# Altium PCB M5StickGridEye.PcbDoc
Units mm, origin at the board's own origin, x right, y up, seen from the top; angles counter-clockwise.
Board outline 20 x 22 mm, 2 copper layers (Top Layer, Bottom Layer); 11 components, 8 nets, 47 pads, 13 vias.
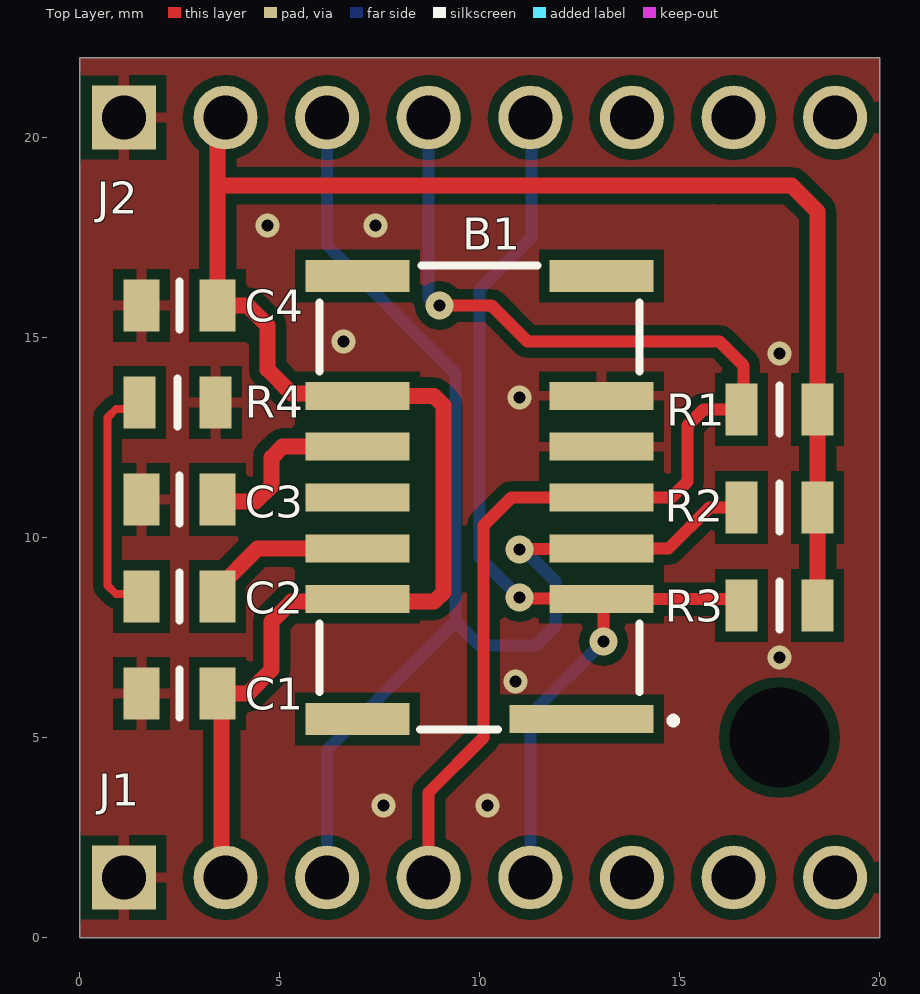
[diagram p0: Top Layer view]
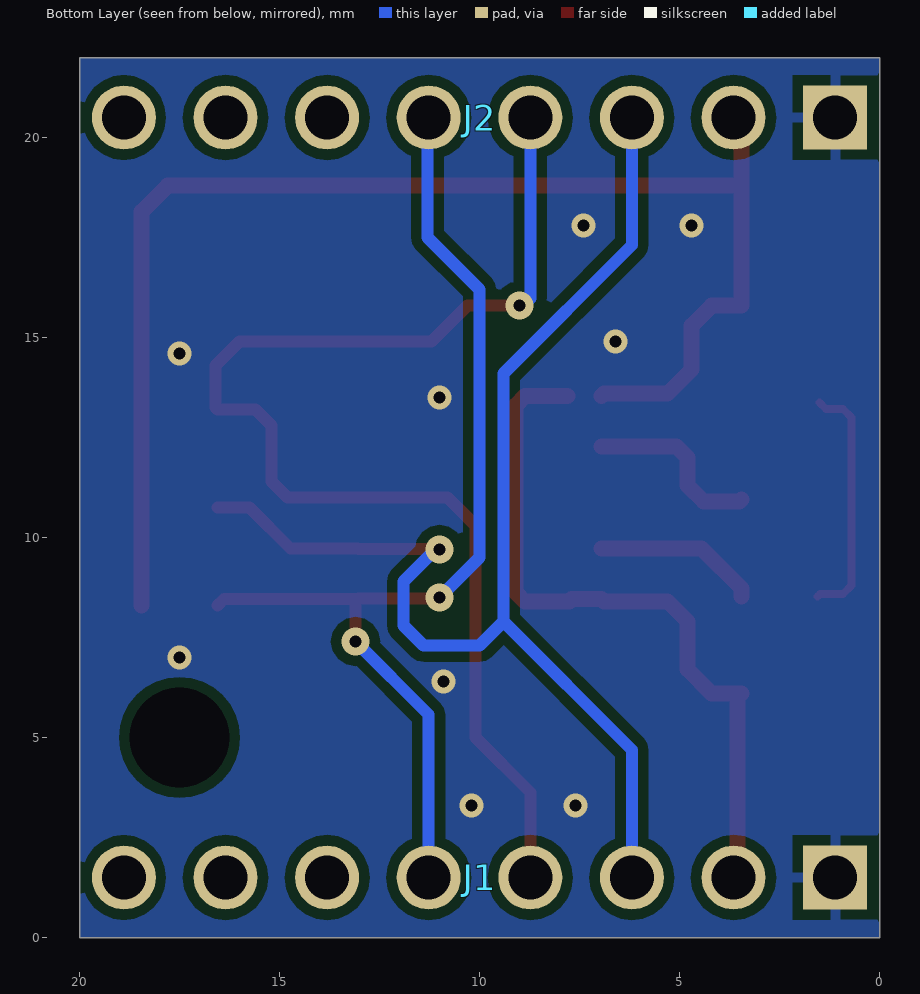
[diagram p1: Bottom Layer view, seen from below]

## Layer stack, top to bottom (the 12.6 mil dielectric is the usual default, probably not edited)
Top Solder: solder mask 0.0102, Solder Resist, Dk 3.5
Top Layer: signal copper 0.0356
Dielectric 1: dielectric 0.32, FR-4, Dk 4.8
Bottom Layer: signal copper 0.0356
Bottom Solder: solder mask 0.0102, Solder Resist, Dk 3.5

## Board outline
0,0 0,22 20,22 20,0

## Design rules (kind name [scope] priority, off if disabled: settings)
Clearance [All] p1: gap=0.254 ignorepadtopadclearanceinfootprint=FALSE except(0: Arc-Hole Track-Hole SMDPad-Hole THPad-Hole Via-Hole Fill-Hole Poly-Hole Region-Hole Text-Hole)
PlaneConnect [InNet('GND')] p1: planeconnectstyle=Direct reliefexpansion=0.508 reliefentries=4 reliefconductorwidth=0.254 reliefairgap=0.254
PlaneConnect PlaneConnect_1 [All] p2: planeconnectstyle=Relief reliefexpansion=0.508 reliefentries=4 reliefconductorwidth=0.254 reliefairgap=0.254
PolygonConnect [InNet('GND') vs InNet('GND') And IsVia] p1: connectstyle=Direct reliefconductorwidth=0.254 reliefentries=4 polygonreliefangle="90 Angle" airgapwidth=0.254
PolygonConnect PolygonConnect_1 [All] p2: connectstyle=Relief reliefconductorwidth=0.254 reliefentries=4 polygonreliefangle="90 Angle" airgapwidth=0.254
RoutingVias [All] p1: holewidth=0.3 width=0.7 viastyle="Through Hole" minholewidth=0.3 minwidth=0.7 maxholewidth=0.7 maxwidth=1.27
SolderMaskExpansion [All] p1: expansion=0.102 istentingtop=FALSE
Width [All] p1: maxlimit=1 minlimit=0.1 preferedwidth=0.2 minimp=50.000000 maximp=50.000000 favimp=50.000000
29 further rules are at their usual default settings.

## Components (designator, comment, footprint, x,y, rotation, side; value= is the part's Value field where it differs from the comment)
B1 "AMG8853" AMG8853 10,11 r90 top locked
C1 "C0805" C0805 2.5,6.1 r0 top value=1u
C2 "C0805" C0805 2.5,8.525 r0 top value=1u
C3 "C0805" C0805 2.5,10.95 r0 top value=1.5u
C4 "C0805" C0805 2.5,15.8 r0 top value=1u
J1 "08p" 61300811121 10,1.5 r0 bottom locked
J2 "08p" 61300811021 10,20.5 r0 bottom locked
R1 "R0805" R0805 17.5,13.2 r0 top value=3k3
R2 "R0805" R0805 17.5,10.75 r0 top value=3k3
R3 "R0805" R0805 17.5,8.3 r0 top value=3k3
R4 "R0805" R0805 2.45,13.375 r180 top value=20

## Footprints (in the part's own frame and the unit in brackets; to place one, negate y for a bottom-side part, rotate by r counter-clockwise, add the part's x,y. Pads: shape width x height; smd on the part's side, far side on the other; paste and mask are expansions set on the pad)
61300811021 [mm] "8 pins, 1 row, right angled, gold plating"
  rect 1.6x1.6 hole 1.1: 1(-8.89,0)
  round 1.6 hole 1.1: 2(-6.35,0) 3(-3.81,0) 4(-1.27,0) 5(1.27,0) 6(3.81,0) 7(6.35,0) 8(8.89,0)
  body extent -10.16,-0.29 10.16,10.07, height 3.27
61300811121 [mm] "8 pins, 1 row, straight, gold plating"
  rect 1.6x1.6 hole 1.1: 1(-8.89,0)
  round 1.6 hole 1.1: 2(-6.35,0) 3(-3.81,0) 4(-1.27,0) 5(1.27,0) 6(3.81,0) 7(6.35,0) 8(8.89,0)
  body extent -10.16,-1.27 10.16,1.27, height 8.57
AMG8853 [mm]
  rect 0.7x3.6 smd: 1(-5.54,-2.55)
  rect 0.7x2.6 smd: 2(-2.54,-3.05) 3(-1.27,-3.05) 4(0,-3.05) 5(1.27,-3.05) 6(2.54,-3.05) 9(2.54,3.05) 10(1.27,3.05) 11(0,3.05) 12(-1.27,3.05) 13(-2.54,3.05)
  rect 0.8x2.6 smd: 7(5.54,-3.05) 8(5.54,3.05) 14(-5.54,3.05)
  silkscreen extent -5.8,-4.91 5.8,4, body extent -5.76,-3.97 5.84,4.03, height 4.44
C0805 [mm] "Chip Capacitor, Body 2.0x1.2mm"
  rect 0.9x1.3 smd: 1(-0.95,0) 2(0.95,0)
  silkscreen extent 0,-0.6 0,0.6, body extent -1,-0.6 1,0.6, height 0.8
R0805 [mm] "Chip Resistor, Body 2.0x1.2mm"
  rect 0.8x1.3 smd: 1(-0.95,0) 2(0.95,0)
  silkscreen extent 0,-0.6 0,0.6, body extent -1,-0.6 1,0.6, height 0.5

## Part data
B1: "IR Array Sensor Grid-EYE,5V,High gain Panasonic AMG8853 Grid-EYE Proximity Sensor Infrared Array Sensor, 7m, Maximum of 5 V dc 14-Pin", Manufacturer_Name=Panasonic, RS Part Number=1229752
C1 C2 C3 C4: "Capacitor"
J1: library part 61300811121, "WR-PHD 2.54 mm THT Pin Header, 08p"
J2: library part 61300811021, "WR-PHD 2.54 mm THT Angled Pin Header, 08p"
R1 R2 R3 R4: "Resistor"

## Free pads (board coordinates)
  round 0 hole 2.5 unplated: 23(17.5,5)

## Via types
v1: diameter 0.6, hole 0.3, Top Layer to Bottom Layer, 9 vias
v2: diameter 0.7, hole 0.3, Top Layer to Bottom Layer, 4 vias

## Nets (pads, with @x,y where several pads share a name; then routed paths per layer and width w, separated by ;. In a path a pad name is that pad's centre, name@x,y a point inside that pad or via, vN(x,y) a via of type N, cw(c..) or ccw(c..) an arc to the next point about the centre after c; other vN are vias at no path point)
GND: B1.5 B1.6 C1.1 C3.1 C4.1 J1.1 J2.1 R4.1
  other v1: 7.6,3.3 10.2,3.3 10.9,6.4 17.5,7 11,13.5 17.5,14.6 6.6,14.9 4.7,17.8 7.4,17.8
INT: B1.4 J1.4 J2.4 R1.1 | length 32
  Top Layer w0.3: J1.4 8.73,3.63 10.1,5 10.1,10.3 10.8,11 B1.4 14.8,11 15.2,11.4 15.2,12.8 15.6,13.2 R1.1 16.6,13.25 16.6,14.3 16,14.9 11.2,14.9 10.3,15.8 v2(9,15.8)
  Bottom Layer w0.3: J2.4 8.73,15.976 8.906,15.8 v2(9,15.8)
NetB1_10: B1.10 C3.2 | length 4.5
  Top Layer w0.4: C3.2 3.5,10.9 4.4,10.9 4.8,11.3 4.8,12 5.07,12.27 B1.10
NetB1_12: B1.12 C2.2 | length 4.1
  Top Layer w0.4: C2.2 3.45,8.725 4.455,9.73 B1.12
NetC2_1: C2.1 R4.2 | length 6.1
  Top Layer w0.2: R4.2 1.342,13.217 0.917,13.217 0.7,13 0.7,8.8 0.917,8.583 1.492,8.583 C2.1
SCL: B1.3 J1.3 J2.3 R2.1 | length 32.9
  Top Layer w0.3: v2(11,9.7) 11.015,9.715 13.035,9.715 B1.3 14.73,9.73 15.75,10.75 R2.1
  Bottom Layer w0.3: J1.3 6.19,4.69 9.4,7.9 ; J2.3 6.19,17.31 9.4,14.1 9.4,7.9 ; v2(11,9.7) 11.1,9.7 11.9,8.9 11.9,7.8 11.4,7.3 10,7.3 9.4,7.9
SDA: B1.2 J1.5 J2.5 R3.1 | length 26.7
  Top Layer w0.3: v2(11,8.5) 11.02,8.48 13.03,8.48 B1.2 ; v2(13.1,7.4) 13.1,8.41 B1.2 ; R3.1 16.39,8.46 B1.2
  Bottom Layer w0.3: J1.5@11.077,1.693 J1.5 11.27,5.57 v2(13.1,7.4) ; v2@11.077,8.423 v2(11,8.5) 10,9.5 10,16.2 11.3,17.5 11.3,20.47 J2.5
VCC: B1.9 B1.13 C1.2 C4.2 J1.2 J2.2 R1.2 R2.2 R3.2 | length 53
  Top Layer w0.4: J1.2 3.55,1.6 3.55,6 C1.2 4.2,6.1 4.8,6.7 4.8,7.9 5.3,8.4 6.89,8.4 B1.13 B1.13@7.694,8.46 ; J2.2 3.45,20.3 3.45,18.8 ; B1.9 6.89,13.6 5.3,13.6 4.7,14.2 4.7,15.3 4.2,15.8 C4.2 3.45,18.8 ; B1.13@7.754,8.4 8.866,8.4 9.1,8.634 9.1,13.3 8.86,13.54 B1.9@7.8,13.54 ; 15.8,18.8 3.45,18.8 ; 15.9,18.8 17.8,18.8 18.45,18.15 R1.2 R2.2 R3.2
pads on no net: B1.1 B1.7 B1.8 B1.11 B1.14 J1.6 J1.7 J1.8 J2.6 J2.7 J2.8

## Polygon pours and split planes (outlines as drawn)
GND on Top Layer "GND_T" (solid, pour order 2): 0,0 20,0 20,22 0,22
GND on Bottom Layer "GND_B" (solid, pour order 3): 0,0 20,0 20,22 0,22

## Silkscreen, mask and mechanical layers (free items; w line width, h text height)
OUTLINE:
  the board outline again, w0.1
